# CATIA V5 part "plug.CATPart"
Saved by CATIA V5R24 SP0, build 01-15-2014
Part number: Part1
Bounding box of the stored display mesh (mm): x -435 to 0, y -152.322 to 152.322, z -165 to 165
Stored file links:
  D:\OneDrive\01_COURSE WORK\2019-1\CAD\models\plug.CATPart
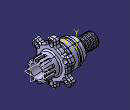
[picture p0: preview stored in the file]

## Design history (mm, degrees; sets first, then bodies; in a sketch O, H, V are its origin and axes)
Body1 (main body)
  Sketch1 on zx-plane, origin (0, 0, 0), H (-1, 0, 0), V (0, 0, 1)
    point P1 (0, 75)
    line L1 (0, 75) -> (110, 75)
    line L2 (110, 75) -> (110, 95)
    line L3 (110, 95) -> (175, 95)
    point P4 (175, 95)
    line L4 (175, 95) -> (177.0711, 90)
    line L5 (177.0711, 90) -> (192.9289, 90)
    line L6 (192.9289, 90) -> (195, 95)
    point P7 (195, 95)
    line L7 (195, 95) -> (230, 95)
    point P8 (230, 95)
    line L8 (230, 95) -> (232.0711, 90)
    point P9 (232.0711, 90)
    line L9 (232.0711, 90) -> (247.9289, 90)
    line L10 (247.9289, 90) -> (250, 95)
    point P11 (250, 95)
    line L11 (250, 95) -> (265, 95)
    line L12 (265, 95) -> (265, 80)
    line L13 (265, 80) -> (305, 80)
    line L14 (305, 80) -> (305, 50)
    line L15 (305, 50) -> (435, 50)
    point P16 (435, 50)
    axis line L16 (0, 0) -> (435, 0)
    point P17 (0, 0)
    line L17 (435, 50) -> (435, 0)
    line L18 (0, 75) -> (0, 0)
    distance L1 H = 75
    distance V L2 = 110
    distance L3 H = 95
    distance L5 L3 = 5
    angle L4 L6 = 45
    angle L4 L5 = 67.5
    length L7 = 35
    distance L2 L12 = 155
    distance P8 P11 = 20
    length L11 = 15
    angle L8 L10 = 45
    angle L8 L9 = 67.5
    distance L13 L16 = 80
    distance L15 L16 = 50
    distance P16 V = 435
    distance L14 L12 = 40
    distance P7 P4 = 20
    coincidence: P1 V, P7 L3, P9 L5, P11 L3, P17 H
    horizontal: L1 H, L3 H, L5 H, L7 H, L9 H, L11 H, L13 H, L15 H, L16 H
    vertical: L2 V, L12 V, L14 V, L17 V, L18 V
  Shaft1: profile Sketch1, axis Sketch1.L16, angle 360
  Sketch2 on yz-plane, origin (0, 0, 0), H (0, 1, 0), V (0, 0, 1)
    line L1 (-10, 80.97) -> (-10, 60)
    line L2 (-10, 60) -> (10, 60)
    line L3 (10, 60) -> (10, 80.97)
    distance L3 L1 = 20
    distance L2 H = 60
    vertical: L1 V, L3 V
    horizontal: L2 H
    symmetry: L3 L1 V
  Pocket1: profile Sketch2, direction (-1, 0, 0), length 70
  CircPattern1: of Pocket1, instances 12, angular step 30, axis from face of Shaft1 from Sketch1.L18
  Sketch3 on zx-plane, origin (0, 0, 0), H (-1, 0, 0), V (0, 0, 1)
    line L1 (420, 40) -> (420, 62.594)
    point P1 (420, 40)
    reference projected line E1 (435, 50) -> (435, -50) from edge [face of Shaft1 from Sketch1.L15 | face of Shaft1 from Sketch1.L17]
    reference projected line E2 through (0, 0) direction (1, 0) from axis of face of Shaft1 from Sketch1.L15
    distance L1 E1 = 15
    distance P1 E2 = 40
    vertical: L1 V
  Groove1: profile Sketch3, axis axis of face of Shaft1 from Sketch1.L15, angle 360, thin wall 10
  RectPattern1: of Groove1, direction 1 instances 6, spacing 20, along axis of face of Shaft1 from Sketch1.L15 reversed
  Chamfer1: length 8, angle 45, on edge [face of Shaft1 from Sketch1.L15 | face of Shaft1 from Sketch1.L17]
  Chamfer2: length 5, angle 45, on edge [face of Shaft1 from Sketch1.L13 | face of Shaft1 from Sketch1.L14]
  Sketch4 on face of Shaft1 from Sketch1.L14, origin (-305, 0, 0), H (0, -1, 0), V (0, 0, 1)
    point P1 (0, 62)
    distance P1 H = 62
    coincidence: P1 V
  Sketch5 on face of Shaft1 from Sketch1.L14, origin (-305, 0, 62), H (0, 1, 0), V (0, 0, -1)
    point P1 (0, 0)
    reference projected point E1 (0, 0) from Sketch4.P1
    coincidence: E1 P1
  Hole1: placed by Sketch5, at (-305, 0, 62) direction (1, 0, 0), diameter 10, depth 20, V-bottom angle 120, counterbore diameter 15, counterbore depth 5
  CircPattern2: of Hole1, instances 6, angular step 60, axis from face of Shaft1 from Sketch1.L14
  Sketch6 on zx-plane, origin (0, 0, 0), H (-1, 0, 0), V (0, 0, 1)
    line L1 (-14.5367, 50) -> (85, 50)
    point P2 (85, 50)
    line L2 (85, 50) -> (100, 20)
    point P3 (100, 20)
    line L3 (100, 20) -> (210, 20)
    point P4 (210, 20)
    line L4 (210, 20) -> (225, 30)
    point P5 (225, 30)
    line L5 (225, 30) -> (445.8544, 30)
    axis line L6 (-20.8796, 0) -> (461.7117, 0)
    point P7 (-20.8796, 0)
    distance L1 H = 50
    distance L3 H = 20
    distance L5 L6 = 30
    distance P2 V = 85
    distance P3 V = 100
    distance P5 V = 225
    distance P4 V = 210
    horizontal: L1 H, L3 H, L5 H, L6 H
    coincidence: P7 H
  Groove2: profile Sketch6, axis Sketch6.L6, angle 360
  Body2
    Sketch7 on yz-plane, origin (0, 0, 0), H (0, 1, 0), V (0, 0, 1)
      circle A1 centre (0, 0) radius 120
      radius A1 = 120
    Pad1: profile Sketch7, direction (-1, 0, 0), length 155, opposite side length -110
    Sketch8 on yz-plane, origin (0, 0, 0), H (0, 1, 0), V (0, 0, 1)
      line L1 (-30, 165) -> (30, 165)
      line L2 (30, 165) -> (30, 105.138)
      line L3 (30, 105.138) -> (-30, 105.138)
      line L4 (-30, 105.138) -> (-30, 165)
      distance L2 L4 = 60
      distance L1 H = 165
      horizontal: L1 H, L3 H
      vertical: L2 V, L4 V
      symmetry: L2 L4 V
    Pad2: profile Sketch8, direction (-1, 0, 0), length 155, opposite side length -110
    Sketch9 on face of Pad2, origin (-110, 0, 0), H (0, 1, 0), V (0, 0, 1)
      construction line L1 (0, 135) -> (0, 120)
      point P1 (0, 135)
      point P2 (0, 120)
      line L2 (15, 135) -> (15, 120)
      line L3 (-15, 120) -> (-15, 135)
      arc A1 centre (0, 120) radius 15 from (15, 120) to (-15, 120) cw
      arc A2 centre (0, 135) radius 15 from (-15, 135) to (15, 135) cw
      distance L1 L2 = 15
      length L1 = 15
      distance P2 H = 120
      coincidence: P1 V
      vertical: L1 V
      tangency: A1 L2, A2 L2, A1 L3, A2 L3
    Pocket2: profile Sketch9, direction (-1, 0, 0), through (limit type 6)
    CircPattern3: of Pad2, Pocket2, instances 6, angular step 60, axis from face of Pad2
    Fillet1: radius 15, on edge [face of Pad2 from Sketch8.L2 | face of Pad2 from Sketch8.L1]; edge [face of Pad2 from Sketch8.L1 | face of Pad2 from Sketch8.L4]; edge [face of CircPattern3 | face of CircPattern3] (x10)
    Fillet2: radius 18, on edge [face of Pad2 from Sketch8.L2 | face of Pad1 from Sketch7.A1]; edge [face of Pad1 from Sketch7.A1 | face of Pad2 from Sketch8.L4]; edge [face of CircPattern3 | face of Pad1 from Sketch7.A1] (x5); edge [face of Pad1 from Sketch7.A1 | face of CircPattern3] (x5)
    Fillet3: radius 10, on edge [face of Pad1 from Sketch7.A1 | face of CircPattern3]; edge [face of CircPattern3 | face of Pad1 from Sketch7.A1]
  Trim1: tool Body2
  Fillet4: radius 10, on edge [face of Shaft1 from Sketch1.L1 | face of Shaft1]
  Fillet5: radius 5, on edge [face of Shaft1 from Sketch1.L3 | face of CircPattern3]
